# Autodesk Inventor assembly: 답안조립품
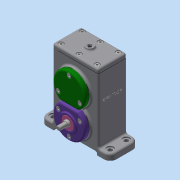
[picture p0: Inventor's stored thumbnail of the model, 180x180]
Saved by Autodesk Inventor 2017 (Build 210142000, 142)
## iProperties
Part Number: 답안조립품
Material: 일반
Document SubType Name: Assembly
Designer: 222
Mass: 1462.99 g
Surface Area: 1578.54 cm^2
Volume: 385.291 cm^3
Density: 3.7971 g/cm^3
Author: 222
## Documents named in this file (24)
- C:\Users\222\Desktop\600506V1017\답안조립품.iam
- C:\Users\222\Desktop\600506V1017\본체.ipt
- C:\Users\222\Desktop\600506V1017\Ű 4 x 4 x 12.ipt
- C:\Users\222\Desktop\600506V1017\Ű 5 x 5 x 12.ipt
- C:\Users\222\Desktop\600506V1017\개스킷 A.ipt
- C:\Users\222\Desktop\600506V1017\개스킷 B.ipt
- C:\Users\222\Desktop\600506V1017\개스킷 C.ipt
- C:\Users\222\Desktop\600506V1017\베어링 6001.ipt
- 베어링 6001.ipt
- C:\Users\222\Desktop\600506V1017\베어링 6002.ipt
- 베어링 6002.ipt
- C:\Users\222\Desktop\600506V1017\볼트 M4.ipt
- C:\Users\222\Desktop\600506V1017\스퍼기어 A.ipt
- C:\Users\222\Desktop\600506V1017\스퍼기어 B.ipt
- C:\Users\222\Desktop\600506V1017\오일 실 10 20 7.ipt
- C:\Users\222\Desktop\600506V1017\오일 실 12 22 7.ipt
- C:\Users\222\Desktop\600506V1017\축 A.ipt
- C:\Users\222\Desktop\600506V1017\축 B.ipt
- C:\Users\222\Desktop\600506V1017\칼라.ipt
- C:\Users\222\Desktop\600506V1017\커버 A.ipt
- C:\Users\222\Desktop\600506V1017\커버 B.ipt
- C:\Users\222\Desktop\600506V1017\커버 C.ipt
- C:\Users\222\Desktop\600506V1017\커버 D.ipt
- C:\Users\222\Desktop\600506V1017\커버 E.ipt
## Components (7 placed, 5 different names)
1. Ű 4 x 4 x 12:1
2. Ű 5 x 5 x 12:1
3. 개스킷 A:1
4. 개스킷 B:1
5. 개스킷 C:1
6. 개스킷 B:2
7. 개스킷 B:3
